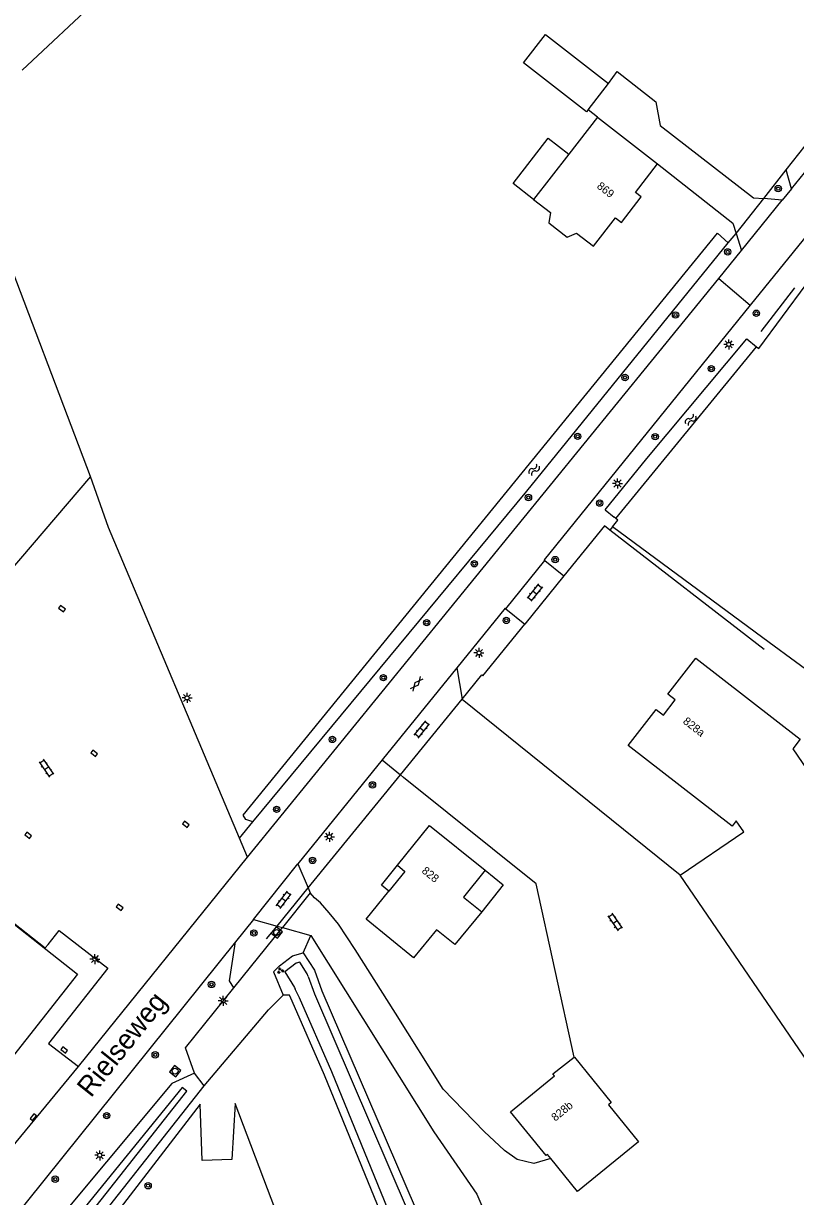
# Model space of a CAD drawing. Extents: x 126000 to 131009, y 393000 to 395500.
# Drawn here: x 130441.7 to 130538.2, y 393591.8 to 393738.4 of the extents above; entities that cross this region are included whole.
import ezdxf

# ---------------------------------------------------------------- set-up
doc = ezdxf.new("R2010")
doc.units = 0
for name, color, linetype in [('gg-afsc-hekwerk', 7, 'Continuous'), ('gg-anno-huisnummerreeks BGT', 7, 'Continuous'), ('gg-anno-openbare ruimte label', 7, 'Continuous'), ('gg-bbg-bijgebouw', 7, 'Continuous'), ('gg-bbg-hoofdgebouw', 7, 'Continuous'), ('gg-bbg-luifel en loopbrug', 7, 'Continuous'), ('gg-bbg-onder overbouw', 7, 'Continuous'), ('gg-bbg-pand overbouw', 7, 'Continuous'), ('gg-knt-bronhoudergrens', 7, 'Continuous'), ('gg-knt-verharding', 7, 'Continuous'), ('gg-kntw-bovenkant insteek waterloop', 7, 'Continuous'), ('gg-kntw-waterlijn', 7, 'Continuous'), ('gg-kwrk-duiker nz buis', 7, 'Continuous'), ('gt-bbg-plantopografie pand', 7, 'Continuous'), ('gt-grn-groengrens', 7, 'Continuous'), ('gt-grn-vlakafsluiter', 7, 'Continuous'), ('gt-grn-weggrens', 7, 'Continuous'), ('gt-symb-boom', 7, 'Continuous'), ('gt-symb-gesloten verharding', 7, 'Continuous'), ('gt-symb-groenvak', 7, 'Continuous'), ('gt-symb-klinker verharding', 7, 'Continuous'), ('gt-symb-kolk', 7, 'Continuous'), ('gt-symb-lichtmast', 7, 'Continuous'), ('gt-symb-rioolschacht', 7, 'Continuous'), ('gt-symb-watersymbool', 7, 'Continuous'), ('gx-grn-maaiveld', 7, 'Continuous')]:
    doc.layers.add(name, color=color, linetype=linetype)

# ---------------------------------------------------------------- blocks, each defined once
blk = doc.blocks.new('gt0-BOOM')
at = {"layer": 'gt-symb-boom'}
for radius in [0.4, 0.2]:
    blk.add_circle((0, 0), radius, dxfattribs=at)
blk = doc.blocks.new('gt0-LMAST')
at = {"layer": 'gt-symb-lichtmast'}
for p, q in [((-0.18, 0.17), (-0.45, 0.44)), ((0, 0.25), (0, 0.62)), ((0.17, 0.17), (0.44, 0.44)), ((-0.25, 0), (-0.63, 0)), ((-0.18, -0.18), (-0.45, -0.45)), ((0, -0.25), (0, -0.63)), ((0.44, -0.45), (0.17, -0.18)), ((0.25, 0), (0.62, 0))]:
    blk.add_line(p, q, dxfattribs=at)
blk.add_circle((0, 0), 0.25, dxfattribs=at)
blk = doc.blocks.new('gt0-WA')
at = {"layer": 'gt-symb-watersymbool'}
for centre, start, end in [((-0.32, 0.02), 28.0725, 151.9275), ((0.43, 0.42), 208.0725, 331.9275), ((-0.32, -0.43), 28.0725, 151.9275), ((0.43, -0.03), 208.0725, 331.9275)]:
    blk.add_arc(centre, 0.425, start, end, dxfattribs=at)
blk = doc.blocks.new('gt0-KL1')
at = {"layer": 'gt-symb-klinker verharding'}
for p, q in [((-1.15, 0.3), (1.15, 0.3)), ((-1, -0.3), (-1, 0.3)), ((-0.5, 0.3), (-0.5, 0.45)), ((0, -0.3), (0, 0.3)), ((0.5, 0.3), (0.5, 0.45)), ((1, -0.3), (1, 0.3)), ((-1.15, -0.3), (1.15, -0.3)), ((-0.5, -0.45), (-0.5, -0.3)), ((0.5, -0.45), (0.5, -0.3))]:
    blk.add_line(p, q, dxfattribs=at)
blk = doc.blocks.new('gt0-GRVAK')
at = {"layer": 'gt-symb-groenvak'}
for p, q in [((-0.11, 0.19), (-0.23, 0.24)), ((-0.18, 0.15), (0.09, 0.15)), ((-0.09, 0.21), (-0.16, 0.32)), ((-0.05, 0.21), (-0.05, 0.39)), ((0, 0.21), (0.06, 0.32)), ((0.01, 0.19), (0.13, 0.24)), ((0.26, -0.05), (0.2, 0.06)), ((0.3, -0.05), (0.3, 0.13)), ((0.35, -0.05), (0.41, 0.06)), ((-0.25, -0.23), (-0.36, -0.18)), ((-0.32, -0.26), (-0.05, -0.26)), ((-0.23, -0.21), (-0.29, -0.1)), ((-0.18, -0.2), (-0.18, -0.02)), ((-0.14, -0.21), (-0.07, -0.1)), ((-0.12, -0.23), (0, -0.18)), ((0.24, -0.07), (0.12, -0.02)), ((0.17, -0.11), (0.44, -0.11)), ((0.37, -0.07), (0.49, -0.02))]:
    blk.add_line(p, q, dxfattribs=at)
blk = doc.blocks.new('gt0-RS')
at = {"layer": 'gt-symb-rioolschacht'}
blk.add_lwpolyline([(-0.5, -0.5), (0.5, -0.5), (0.5, 0.5), (-0.5, 0.5)], close=True, dxfattribs=at)
blk.add_circle((0, 0), 0.375, dxfattribs=at)
blk = doc.blocks.new('gt0-KOLK')
at = {"layer": 'gt-symb-kolk'}
blk.add_lwpolyline([(0, 0), (0.38, 0), (0.38, 0.4), (-0.37, 0.4), (-0.37, 0), (0, 0)], dxfattribs=at)
blk = doc.blocks.new('gt0-GESVH1')
at = {"layer": 'gt-symb-gesloten verharding'}
for p, q in [((-0.99, -0.26), (0.01, 0.24)), ((0.01, -0.26), (-0.99, 0.24)), ((0.01, 0.24), (1.01, -0.26)), ((1.01, 0.24), (0.01, -0.26))]:
    blk.add_line(p, q, dxfattribs=at)

msp = doc.modelspace()

# ---------------------------------------------------------------- linework, layer by layer
at = {"layer": 'gg-afsc-hekwerk'}
for p, q in [((130441.55, 393732.61), (130518.08, 393804.24)), ((130534.29, 393660.19), (130515.02, 393675.11)), ((130509.27, 393669.38), (130504.38, 393663.35)), ((130509.27, 393669.38), (130504.38, 393663.35)), ((130488.84, 393644.52), (130496.54, 393653.96)), ((130477.3, 393630.38), (130488.84, 393644.52)), ((130473.42, 393625.62), (130477.3, 393630.38)), ((130472.11, 393624), (130473.42, 393625.62))]:
    msp.add_line(p, q, dxfattribs=at)
for points in [[(130515.02, 393675.11), (130514.35, 393675.63), (130509.27, 393669.38)], [(130515.02, 393675.11), (130514.35, 393675.63), (130509.27, 393669.38)], [(130496.54, 393653.96), (130499.02, 393657), (130499.14, 393656.9), (130504.38, 393663.35)], [(130496.54, 393653.96), (130499.02, 393657), (130499.14, 393656.9), (130504.38, 393663.35)]]:
    msp.add_lwpolyline(points, dxfattribs=at)
at = {"layer": 'gg-bbg-bijgebouw'}
msp.add_line((130512.29, 393727.62), (130514.86, 393730.94), dxfattribs=at)
msp.add_lwpolyline([(130512.29, 393727.62), (130512.11, 393727.39), (130504.21, 393733.51), (130506.97, 393737.07), (130514.86, 393730.94)], dxfattribs=at)
at = {"layer": 'gg-bbg-hoofdgebouw'}
for p, q in [((130513.47, 393726.71), (130509.89, 393722.1)), ((130513.47, 393726.71), (130520.96, 393720.88)), ((130509.89, 393722.1), (130505.49, 393716.44)), ((130557.26, 393582.98), (130523.82, 393631.98))]:
    msp.add_line(p, q, dxfattribs=at)
for points in [[(130505.49, 393716.44), (130507.6, 393714.79), (130507.37, 393713.53), (130509.69, 393711.74), (130510.86, 393712.21), (130512.97, 393710.59), (130515.71, 393714.15), (130516.46, 393713.57), (130518.93, 393716.75), (130518.23, 393717.32), (130520.96, 393720.88)], [(130523.82, 393631.98), (130531.76, 393637.4), (130530.83, 393638.76), (130530.32, 393638.12), (130517.32, 393648.2), (130520.8, 393652.68), (130521.71, 393651.98), (130523.18, 393653.89), (130522.27, 393654.59), (130525.75, 393659.08), (130538.8, 393648.97), (130537.9, 393647.78), (130540.78, 393643.55), (130548.6, 393648.89)], [(130488.46, 393633.22), (130492.45, 393638.19), (130499.42, 393632.59)], [(130499.01, 393627.41), (130495.62, 393623.31), (130493.33, 393625.16), (130490.49, 393621.66), (130484.56, 393626.48), (130487.4, 393629.98)], [(130507.62, 393596.57), (130507.22, 393597.07), (130507.04, 393596.95), (130502.61, 393602.39), (130508.11, 393606.9), (130507.9, 393607.15), (130510.54, 393609.21)], [(130510.54, 393609.21), (130510.58, 393609.24), (130515.2, 393603.58), (130514.83, 393603.28), (130518.61, 393598.65), (130510.98, 393592.42), (130507.62, 393596.57)]]:
    msp.add_lwpolyline(points, dxfattribs=at)
at = {"layer": 'gg-bbg-luifel en loopbrug'}
msp.add_lwpolyline([(130505.49, 393716.44), (130502.91, 393718.44), (130507.31, 393724.11), (130509.89, 393722.1)], dxfattribs=at)
at = {"layer": 'gg-bbg-onder overbouw'}
for points in [[(130488.46, 393633.22), (130489.4, 393632.44), (130487.4, 393629.98)], [(130499.42, 393632.59), (130496.73, 393629.24), (130499.01, 393627.41)]]:
    msp.add_lwpolyline(points, dxfattribs=at)
at = {"layer": 'gg-bbg-pand overbouw'}
for points in [[(130487.4, 393629.98), (130486.47, 393630.73), (130488.46, 393633.22)], [(130499.42, 393632.59), (130501.7, 393630.75), (130499.01, 393627.41)]]:
    msp.add_lwpolyline(points, dxfattribs=at)
at = {"layer": 'gg-knt-bronhoudergrens'}
for p, q in [((130534.95, 393661.07), (130515.36, 393675.53)), ((130549.25, 393650.51), (130534.95, 393661.07))]:
    msp.add_line(p, q, dxfattribs=at)
msp.add_lwpolyline([(130473.71, 393588.82), (130468.16, 393603.42), (130467.77, 393596.45), (130464.05, 393596.3), (130463.82, 393603.37), (130444.33, 393578.06), (130436.76, 393567.32), (130422.05, 393550.43), (130421.53, 393548.71), (130421.79, 393546.59), (130429.46, 393524.77), (130431.25, 393524.16)], dxfattribs=at)
at = {"layer": 'gg-knt-verharding'}
for p, q in [((130560.51, 393737.77), (130532.55, 393703.22)), ((130513.47, 393726.71), (130512.29, 393727.62)), ((130537.72, 393717.77), (130542.94, 393724.21)), ((130537.72, 393717.77), (130537.07, 393720.12)), ((130537.72, 393717.77), (130536.57, 393716.35)), ((130531.49, 393710.07), (130536.57, 393716.35)), ((130536.57, 393716.35), (130534.26, 393716.54)), ((130530.82, 393712.17), (130531.49, 393710.07)), ((130528.63, 393706.55), (130531.49, 393710.07)), ((130469.72, 393634.23), (130528.63, 393706.55)), ((130528.63, 393706.55), (130532.55, 393703.22)), ((130532.55, 393703.22), (130506.79, 393671.39)), ((130450.09, 393681.82), (130439.89, 393669.86)), ((130502.02, 393665.27), (130506.88, 393671.32)), ((130506.79, 393671.39), (130506.88, 393671.32)), ((130506.88, 393671.32), (130509.27, 393669.38)), ((130501.91, 393665.36), (130495.88, 393657.91)), ((130501.91, 393665.36), (130502.02, 393665.27)), ((130502.02, 393665.27), (130504.38, 393663.35)), ((130495.88, 393657.91), (130486.56, 393646.4)), ((130495.88, 393657.91), (130496.54, 393653.96)), ((130496.54, 393653.96), (130496.55, 393653.92)), ((130523.82, 393631.98), (130496.55, 393653.92)), ((130486.56, 393646.4), (130476.03, 393633.39)), ((130486.56, 393646.4), (130488.84, 393644.52)), ((130488.84, 393644.52), (130489.22, 393644.2)), ((130469.72, 393634.23), (130468.71, 393636.62)), ((130448.6, 393608.05), (130469.72, 393634.23)), ((130470.45, 393626.44), (130476.03, 393633.39)), ((130476.03, 393633.39), (130477.3, 393630.38)), ((130477.56, 393629.77), (130474.08, 393625.44)), ((130477.3, 393630.38), (130477.56, 393629.77)), ((130470.45, 393626.44), (130468.21, 393623.66)), ((130470.45, 393626.44), (130473.42, 393625.62)), ((130473.42, 393625.62), (130474.08, 393625.44)), ((130474.08, 393625.44), (130477.63, 393624.43)), ((130468.21, 393623.66), (130437.83, 393585.84)), ((130436.08, 393592.94), (130448.6, 393608.05))]:
    msp.add_line(p, q, dxfattribs=at)
for points in [[(130514.86, 393730.94), (130515.95, 393732.44), (130520.77, 393728.65), (130521.3, 393725.67), (130532.97, 393716.64), (130534.26, 393716.54)], [(130520.96, 393720.88), (130530.41, 393713.48), (130530.82, 393712.17)], [(130468.71, 393636.62), (130452.32, 393675.43), (130450.09, 393681.82)], [(130510.54, 393609.21), (130505.81, 393630.89), (130489.22, 393644.2)], [(130507.62, 393596.57), (130505.53, 393595.93), (130503.41, 393596.45), (130501.86, 393597.55), (130499.32, 393599.95), (130494.2, 393605.23), (130488.24, 393614.72), (130483.16, 393622.69), (130481.08, 393625.84), (130479.93, 393627.25), (130478.83, 393628.5), (130478.08, 393629.13), (130477.56, 393629.77)], [(130477.63, 393624.43), (130493.01, 393599.91), (130498.37, 393592.09), (130499.48, 393589.58), (130500.26, 393586.97), (130500.58, 393585.04), (130501.13, 393583.7), (130502.8, 393584.36), (130504.67, 393584.4), (130506.72, 393583.72), (130508.16, 393582.51), (130509.63, 393579.36)]]:
    msp.add_lwpolyline(points, dxfattribs=at)
at = {"layer": 'gg-kntw-bovenkant insteek waterloop'}
for p, q in [((130514.44, 393677.64), (130515.56, 393676.72)), ((130476.68, 393622.28), (130478.08, 393620.09)), ((130472.98, 393619.89), (130474.18, 393616.99)), ((130474.95, 393616.97), (130474.18, 393616.99)), ((130464.32, 393605.65), (130463.11, 393607.23)), ((130423.17, 393553.54), (130464.32, 393605.65))]:
    msp.add_line(p, q, dxfattribs=at)
for points in [[(130470.37, 393638.63), (130469.5, 393638.93), (130469.16, 393639.49), (130528.46, 393712.21), (130529.8, 393711.01)], [(130470.37, 393638.63), (130504.63, 393679.97), (130529.8, 393711.01)], [(130514.44, 393677.64), (130519.64, 393684.07), (130532.14, 393699.03)], [(130472.98, 393619.89), (130473.71, 393620.63), (130475.35, 393621.89), (130476.68, 393622.28)], [(130478.08, 393620.09), (130479.02, 393617.53), (130495.33, 393579.59), (130505.47, 393552.56), (130507.65, 393547.93), (130508.04, 393546.66), (130508.68, 393545.98)], [(130505.25, 393545.17), (130505.07, 393546.38), (130493.73, 393571.8), (130479.35, 393606.99), (130475.3, 393616.24), (130474.95, 393616.97)], [(130463.11, 393607.23), (130460.24, 393605.93), (130419.39, 393556.98)]]:
    msp.add_lwpolyline(points, dxfattribs=at)
at = {"layer": 'gg-kntw-waterlijn'}
msp.add_line((130461.53, 393605.44), (130419.61, 393553.79), dxfattribs=at)
for points in [[(130477.3, 393619.31), (130477.18, 393619.64), (130476.24, 393621.1), (130475.81, 393620.98), (130474.37, 393619.88), (130475.58, 393617.94), (130475.69, 393617.71)], [(130477.3, 393619.31), (130478.09, 393617.16), (130494.4, 393579.21), (130504.54, 393552.17), (130506.72, 393547.57), (130507.31, 393545.65)], [(130506.22, 393545.4), (130506.04, 393546.66), (130494.65, 393572.2), (130480.27, 393607.38), (130476.21, 393616.66), (130475.69, 393617.71)], [(130421.11, 393553.03), (130462.13, 393604.97), (130461.53, 393605.44)]]:
    msp.add_lwpolyline(points, dxfattribs=at)
at = {"layer": 'gg-kwrk-duiker nz buis'}
msp.add_line((130538.09, 393705.39), (130533.9, 393699.92), dxfattribs=at)
at = {"layer": 'gt-bbg-plantopografie pand'}
msp.add_lwpolyline([(130400.56, 393621.8), (130394.47, 393626.5), (130411.81, 393648.5), (130448.46, 393619.62), (130420.13, 393583.66), (130393.51, 393604.64), (130404.45, 393618.8)], dxfattribs=at)
at = {"layer": 'gt-grn-groengrens'}
for p, q in [((130450.09, 393681.82), (130433.62, 393725.18)), ((130534.26, 393716.54), (130537.07, 393720.12)), ((130529.8, 393711.01), (130530.82, 393712.17)), ((130515.36, 393675.53), (130515.02, 393675.11)), ((130468.71, 393636.62), (130470.37, 393638.63)), ((130467.99, 393617.88), (130474.08, 393625.44)), ((130476.68, 393622.28), (130477.63, 393624.43))]:
    msp.add_line(p, q, dxfattribs=at)
for points in [[(130467.99, 393617.88), (130467.48, 393618.75), (130468.21, 393623.66)], [(130463.11, 393607.23), (130461.98, 393610.39), (130467.99, 393617.88)], [(130464.32, 393605.65), (130472.36, 393615.14), (130474.18, 393616.99)]]:
    msp.add_lwpolyline(points, dxfattribs=at)
at = {"layer": 'gt-grn-vlakafsluiter'}
msp.add_line((130444.44, 393622.89), (130444.78, 393623.33), dxfattribs=at)
for points in [[(130431.1, 393658.99), (130418.45, 393643.33), (130444.44, 393622.89)], [(130444.78, 393623.33), (130446.16, 393625.08), (130452.27, 393620.36), (130444.85, 393610.93), (130448.6, 393608.05)]]:
    msp.add_lwpolyline(points, dxfattribs=at)
at = {"layer": 'gt-grn-weggrens'}
for p, q in [((130537.07, 393720.12), (130540.23, 393724.14)), ((130530.82, 393712.17), (130534.26, 393716.54))]:
    msp.add_line(p, q, dxfattribs=at)
at = {"layer": 'gx-grn-maaiveld'}
for p, q in [((130533.65, 393697.81), (130539.55, 393705.82)), ((130515.75, 393676.56), (130533.37, 393698.03)), ((130532.14, 393699.03), (130533.37, 393698.03)), ((130533.37, 393698.03), (130533.65, 393697.81)), ((130515.36, 393675.53), (130516.03, 393676.34)), ((130515.75, 393676.56), (130515.56, 393676.72)), ((130516.03, 393676.34), (130515.75, 393676.56))]:
    msp.add_line(p, q, dxfattribs=at)

# ---------------------------------------------------------------- block references
at = {"layer": 'gt-symb-boom'}
for p in [(130536.07, 393717.79), (130529.75, 393709.88), (130523.23, 393701.99), (130533.33, 393702.21), (130527.7, 393695.29), (130516.92, 393694.18), (130511, 393686.82), (130520.68, 393686.79), (130504.84, 393679.18), (130513.75, 393678.48), (130508.18, 393671.42), (130498.07, 393670.9), (130502.07, 393663.82), (130492.12, 393663.53), (130486.7, 393656.66), (130480.33, 393648.94), (130485.34, 393643.26), (130473.36, 393640.2), (130477.85, 393633.82), (130470.52, 393624.75), (130465.22, 393618.32), (130458.18, 393609.52), (130452.11, 393601.92), (130445.68, 393593.98), (130457.29, 393593.16)]:
    msp.add_blockref('gt0-BOOM', p, dxfattribs=at)
at = {"layer": 'gt-symb-gesloten verharding', "rotation": -128.99099404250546}
msp.add_blockref('gt0-GESVH1', (130490.89, 393655.89), dxfattribs=at)
at = {"layer": 'gt-symb-groenvak'}
msp.add_blockref('gt0-GRVAK', (130473.83, 393620.04), dxfattribs=at)
at = {"layer": 'gt-symb-klinker verharding'}
for p, rotation in [((130505.63, 393667.32), -128.74927691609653), ((130491.53, 393650.18), 51.00900595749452), ((130444.58, 393645.36), -55.67439803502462), ((130474.25, 393628.89), 53.13010235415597), ((130515.66, 393626.12), -55.67439803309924)]:
    msp.add_blockref('gt0-KL1', p, dxfattribs=dict(at, rotation=rotation))
at = {"layer": 'gt-symb-kolk'}
for p, rotation in [((130446.4, 393665.14), -37.56859202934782), ((130450.41, 393647.04), -37.568592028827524), ((130461.88, 393638.17), -37.568592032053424), ((130442.16, 393636.8), -37.56859202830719), ((130453.61, 393627.8), -37.56859202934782), ((130446.66, 393609.97), -37.568592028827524), ((130443.08, 393601.59), 50.96448710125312)]:
    msp.add_blockref('gt0-KOLK', p, dxfattribs=dict(at, rotation=rotation))
at = {"layer": 'gt-symb-lichtmast'}
for p in [(130529.89, 393698.32), (130515.98, 393680.93), (130498.66, 393659.76), (130462.16, 393654.13), (130479.96, 393636.78), (130450.65, 393621.49), (130466.68, 393616.27), (130451.24, 393596.96)]:
    msp.add_blockref('gt0-LMAST', p, dxfattribs=at)
at = {"layer": 'gt-symb-rioolschacht'}
for p, rotation in [((130473.37, 393624.81), 51.25072308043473), ((130460.67, 393607.48), 51.25072308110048)]:
    msp.add_blockref('gt0-RS', p, dxfattribs=dict(at, rotation=rotation))
at = {"layer": 'gt-symb-watersymbool', "rotation": 50.8033111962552}
for p in [(130525.09, 393688.85), (130505.52, 393682.6)]:
    msp.add_blockref('gt0-WA', p, dxfattribs=at)

# ---------------------------------------------------------------- texts
at = {"layer": 'gg-anno-huisnummerreeks BGT'}
for s, rotation, p in [('869', 322.1, (130513.31, 393717.93)), ('828a', 322.2, (130524.07, 393651.04)), ('828', 321.3, (130491.41, 393632.37)), ('828b', 39.4, (130508.2, 393601.16))]:
    msp.add_text(s, height=1, rotation=rotation, dxfattribs=at).set_placement(p)
at = {"layer": 'gg-anno-openbare ruimte label'}
msp.add_text('Rielseweg', height=2.5, rotation=51.3, dxfattribs=at).set_placement((130450.14, 393604.07))

doc.saveas('drawing.dxf')
